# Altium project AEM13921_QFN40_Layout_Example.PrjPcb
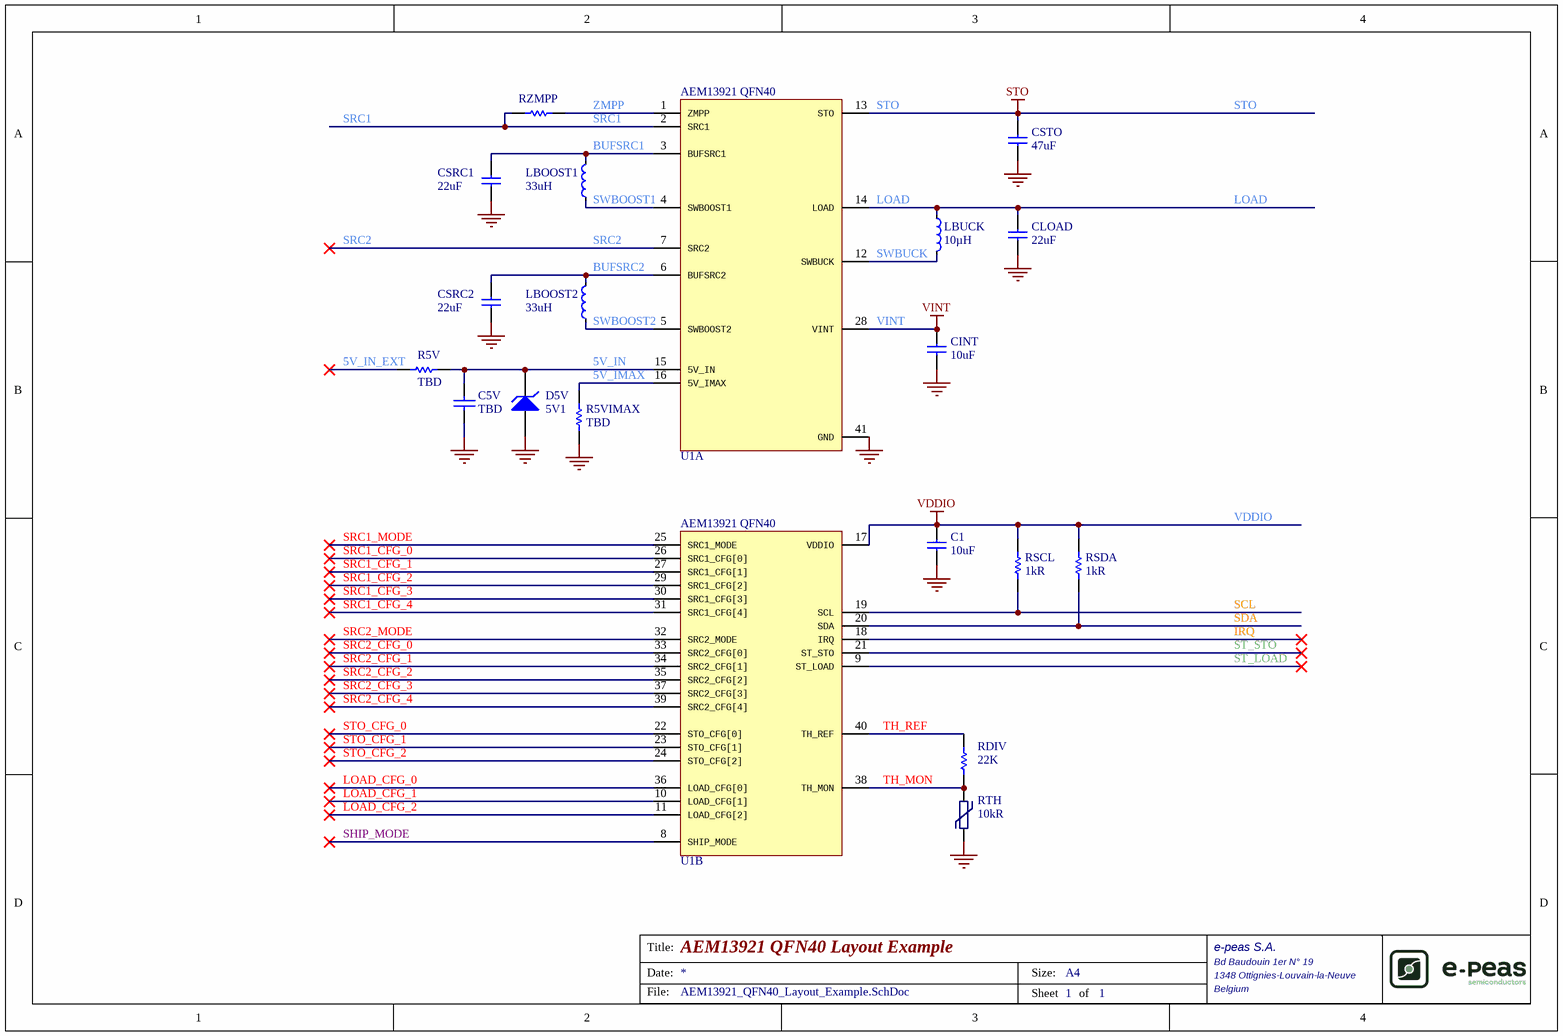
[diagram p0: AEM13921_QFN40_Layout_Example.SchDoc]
Website_Global: https://e-peas.com; Organization_Global: e-peas S.A.; Name: AEM13921 QFN40 Layout Example; Address3_Global: Belgium; Address2_Global: 1348 Ottignies-Louvain-la-Neuve; Address1_Global: Bd Baudouin 1er N° 19
1 sheet, 19 parts. Net scope: global (net labels, ports and power ports of the same name join across sheets).
Board file: AEM13921_QFN40_Layout_Example.PcbDoc

## Sheet AEM13921_QFN40_Layout_Example.SchDoc
size A4; DocumentNumber: 1; SheetNumber: 1; SheetTotal: 1; Organization: e-peas S.A.; Address1: The Gate Business Center; Address2: rue Cattelain 1 b4,; Address3: 1435 Mont-St-Guibert; Address4: Belgium

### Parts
C1  10uF  [0603_[1608]]
C5V  value TBD  [0603_[1608]]  (hidden comment: Cap Ceramic 0603 TBD)
CINT  10uF  [0402_[1005]]
CLOAD  22uF  [0603_[1608]]
CSRC1  22uF  [0603_[1608]]
CSRC2  22uF  [0603_[1608]]
CSTO  47uF  [0603_[1608]]
D5V  5V1  [SOT23-3P  3x1.40mm Pitch=0.915mm diode AK]
LBOOST1  33uH  [Coilcraft-LPS4018]
LBOOST2  33uH  [Coilcraft-LPS4018]
LBUCK  10µH  [Inductor_VLS252012]
R5V  TBD  [Resistor_0603_[1608]]
R5VIMAX  TBD  [Resistor_0603_[1608]]
RDIV  22K  [Resistor_0402]
RSCL  1kR  [Resistor_0603_[1608]]
RSDA  1kR  [Resistor_0603_[1608]]
RTH  10kR  [Resistor_0402]
RZMPP  TBD  [Resistor_0603_[1608]]  (value not drawn)
U1  AEM13921_QFN40  [QFN40_5x5mm_pitch0.4mm_ASE_98A0040QN185]  (value not drawn)  (parts A,B of 2)

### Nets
GND: C1.1 C5V.1 CINT.1 CLOAD.1 CSRC1.1 CSRC2.1 CSTO.1 D5V.A R5VIMAX.1 RTH.1 U1.41(GND)
STO: CSTO.2 U1.13(STO)
VDDIO: C1.2 RSCL.1 RSDA.1 U1.17(VDDIO)
VINT: CINT.2 U1.28(VINT)
5V_IMAX: R5VIMAX.2 U1.16(5V_IMAX)
5V_IN: C5V.2 D5V.K R5V.2 U1.15(5V_IN)
5V_IN_EXT: R5V.1
BUFSRC1: CSRC1.2 LBOOST1.1 U1.3(BUFSRC1)
BUFSRC2: CSRC2.2 LBOOST2.2 U1.6(BUFSRC2)
IRQ: U1.18(IRQ)
LOAD: CLOAD.2 LBUCK.1 U1.14(LOAD)
LOAD_CFG_0: U1.36(LOAD_CFG[0])
LOAD_CFG_1: U1.10(LOAD_CFG[1])
LOAD_CFG_2: U1.11(LOAD_CFG[2])
SCL: RSCL.2 U1.19(SCL)
SDA: RSDA.2 U1.20(SDA)
SHIP_MODE: U1.8(SHIP_MODE)
SRC1: RZMPP.1 U1.2(SRC1)
SRC1_CFG_0: U1.26(SRC1_CFG[0])
SRC1_CFG_1: U1.27(SRC1_CFG[1])
SRC1_CFG_2: U1.29(SRC1_CFG[2])
SRC1_CFG_3: U1.30(SRC1_CFG[3])
SRC1_CFG_4: U1.31(SRC1_CFG[4])
SRC1_MODE: U1.25(SRC1_MODE)
SRC2: U1.7(SRC2)
SRC2_CFG_0: U1.33(SRC2_CFG[0])
SRC2_CFG_1: U1.34(SRC2_CFG[1])
SRC2_CFG_2: U1.35(SRC2_CFG[2])
SRC2_CFG_3: U1.37(SRC2_CFG[3])
SRC2_CFG_4: U1.39(SRC2_CFG[4])
SRC2_MODE: U1.32(SRC2_MODE)
ST_LOAD: U1.9(ST_LOAD)
ST_STO: U1.21(ST_STO)
STO_CFG_0: U1.22(STO_CFG[0])
STO_CFG_1: U1.23(STO_CFG[1])
STO_CFG_2: U1.24(STO_CFG[2])
SWBOOST1: LBOOST1.2 U1.4(SWBOOST1)
SWBOOST2: LBOOST2.1 U1.5(SWBOOST2)
SWBUCK: LBUCK.2 U1.12(SWBUCK)
TH_MON: RDIV.2 RTH.2 U1.38(TH_MON)
TH_REF: RDIV.1 U1.40(TH_REF)
ZMPP: RZMPP.2 U1.1(ZMPP)

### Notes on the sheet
- Title:
- Date:
- Size:
- A4
- File:
- Sheet
- of

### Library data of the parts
C1 = Cap Ceramic 10uF, 10V, 20%, X5R 0603: Manuf: MURATA; Manuf PN: GRM188R61A106ME69D; Package Metric: 1608
C5V = Cap Ceramic 0603 TBD: Package Metric: 1608
CINT = Cap Ceramic 10uF, 6.3V, 20%, X5R, 0402: Manuf: MURATA; Manuf PN: GRM155R60J106ME44D; Package Metric: 1005
CLOAD CSRC1 CSRC2 = Cap Ceramic 22uF, 10V, 20%, X5R 0603: Manuf: MuRata; Manuf PN: GRM188R61A226ME15D; Package Metric: 1608
CSTO = Cap Ceramic 47uF 6.3V +/-20% X5R 0603: Manuf: Murata; Manuf PN: GRM188R60J476ME15D; Package Metric: 1608
D5V = Zener 5.1V 350mW BZX84C5V1-TP: Zener Diode 5.1 V 350 mW ±5% Surface Mount SOT-23; Manuf: Micro Commercial Co; Vbr: 5.1V; I continous: 68mA
LBOOST1 LBOOST2 = Power Inductor 33uH - 0,68A - LPS4018 - Small Symbol: Power Inductor 33uH - 0,68A - LPS4018; Manuf: Coilcraft; Manuf PN: LPS4018-333MRB; Tol: 20%; Rdc: 420mOhms; Self Resonant Frequency: 20MHz; Max DC Current: 800mA
LBUCK = Power Inductor 10µH TDK VLS-CX-1: Manuf PN: VLS252012CX-100M-1; Tol: ±20%; Rdc: 0.482 ohm; Max DC Current: 970 mA
R5V R5VIMAX RZMPP = Resistor TBD - 0603: Mnt: SMD
RDIV = Resistor 22KR - 0402 - 50V: Manuf: Yageo; Manuf PN: RC0402FR-0722KL; P max mW: 63; Mnt: SMD; Tol %: 1%
RSCL RSDA = Resistor 1kOhm - 0603 - 75V - 1%: Manuf: Multicomp; Manuf PN: MCWR06X1001FTL; P max mW: 100; Tol %: 1; V max: 75V; Mnt: SMD; Package Metric: 1608
RTH = Thermistor 10kR CTN 0402: Manuf: Murata; Manuf PN: NCP15XH103J03RC; Mnt: SMD
U1 = AEM13921 QFN40: Manuf: e-peas; Manuf PN: 10AEM13921J0000; Mnt: SMD; Pitch: 0.4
